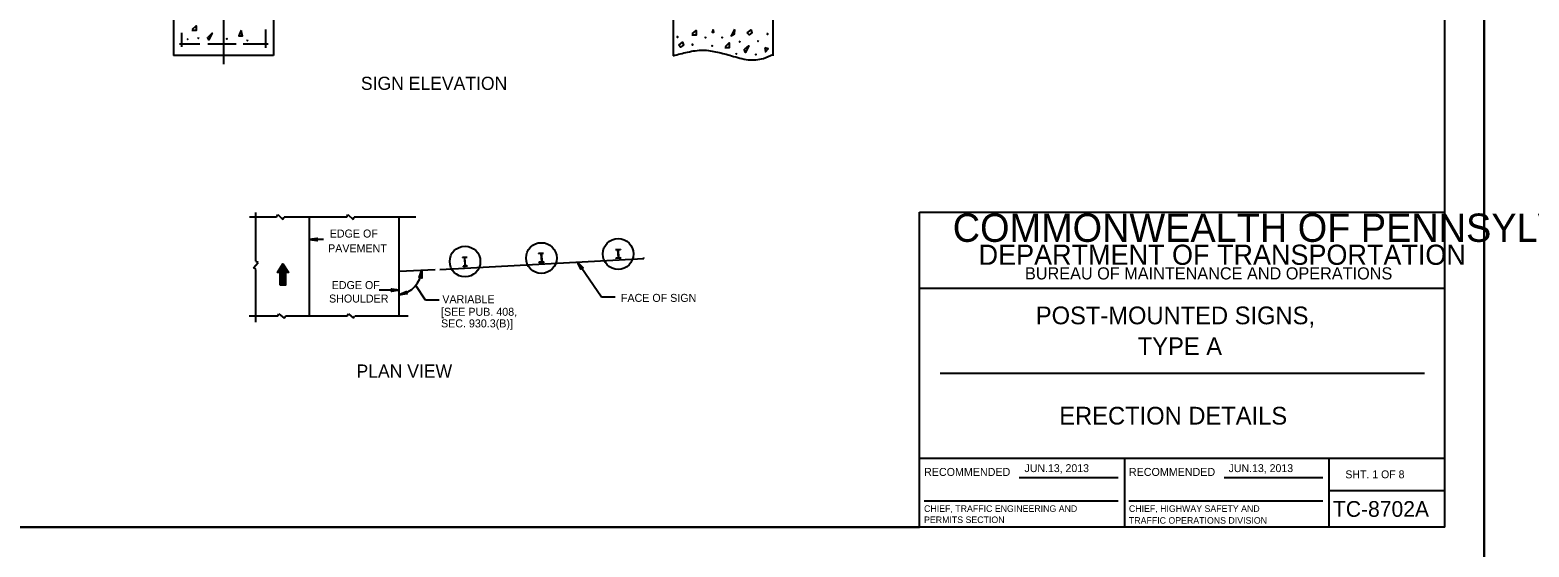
# Model space of a CAD drawing. Extents: x 637580 to 641008, y 294594 to 295782.
# Drawn here: x 637868 to 638438, y 295195 to 295392 of the extents above; entities that cross this region are included whole.
import ezdxf

# ---------------------------------------------------------------- set-up
doc = ezdxf.new("R2010")
doc.units = 0
for name, color, linetype in [('1', 7, 'Continuous'), ('2', 7, 'Continuous'), ('3', 7, 'Continuous'), ('PLT-BNDY', 7, 'Continuous')]:
    doc.layers.add(name, color=color, linetype=linetype)

# ---------------------------------------------------------------- blocks, each defined once
blk = doc.blocks.new('RARROW')
at = {"layer": '3'}
blk.add_lwpolyline([(-2.2695, 0.285), (-2.184875, 0.12075), (0, 0), (-2.2695, 0.285), (-2.38575, 0.384625), (0, 0), (-2.183125, -0.108), (-2.262875, -0.2705), (0, 0), (-2.38575, -0.379125), (-2.262875, -0.2705)], dxfattribs=at)

msp = doc.modelspace()

# ---------------------------------------------------------------- linework, layer by layer
at = {"layer": '1'}
for p, q in [((638406.31, 295202.63), (638406.31, 295766.63)), ((638206.31, 295202.63), (638206.31, 295322.63)), ((638206.31, 295322.63), (638406.31, 295322.63)), ((638406.31, 295293.63), (638206.31, 295293.63)), ((638214.06, 295261.31), (638398.56, 295261.31)), ((638206.31, 295229), (638406.31, 295229)), ((638284.31, 295229), (638284.31, 295202.63)), ((638362.19, 295202.63), (638362.19, 295229)), ((638244.24, 295221.57), (638281.87, 295221.57)), ((638322.24, 295221.57), (638359.87, 295221.57)), ((638362.19, 295216.63), (638406.31, 295216.63)), ((638207.99, 295212.68), (638281.87, 295212.68)), ((638285.99, 295212.68), (638359.87, 295212.68)), ((638406.31, 295202.63), (637620.31, 295202.63)), ((637620.31, 295202.63), (638206.31, 295202.63))]:
    msp.add_line(p, q, dxfattribs=at)
for points in [[(637962.81, 295294.88), (637962.81, 295299.63), (637961.81, 295299.63), (637963.81, 295303), (637965.94, 295299.63), (637964.81, 295299.63), (637964.81, 295294.88), (637962.81, 295294.88)], [(637963.06, 295294.88), (637963.06, 295299.75), (637962.19, 295299.75), (637963.81, 295302.38), (637965.44, 295299.75), (637964.69, 295299.75), (637964.69, 295294.88), (637963.19, 295294.88), (637963.19, 295300.25), (637962.69, 295300), (637963.81, 295301.88), (637965.06, 295300), (637964.31, 295300.25), (637964.31, 295295.25), (637963.44, 295295.25), (637963.44, 295300.5), (637963.81, 295301.13), (637964.31, 295300.5), (637963.81, 295300.5), (637963.81, 295295.38)], [(637963.06, 295294.88), (637962.81, 295294.88)]]:
    msp.add_lwpolyline(points, dxfattribs=at)
at = {"layer": '2'}
for p, q in [((637941.19, 295463.25), (637941.19, 295379)), ((637922.19, 295454.75), (637922.19, 295382.38)), ((637960.31, 295454.13), (637960.31, 295382.38)), ((638112.44, 295420), (638112.44, 295382.25)), ((638150.44, 295409.25), (638150.44, 295382.25)), ((637925.31, 295391), (637925.31, 295385.63)), ((637957.19, 295392.25), (637957.19, 295385.25)), ((637960.31, 295382.38), (637922.19, 295382.38)), ((637932.19, 295386.63), (637924.44, 295386.63)), ((637946.06, 295386.63), (637935.31, 295386.63)), ((637958.19, 295386.63), (637948.69, 295386.63)), ((637961.44, 295320.75), (637951.19, 295320.75)), ((637953.56, 295304), (637953.56, 295322.5)), ((637961.44, 295320.75), (637961.94, 295321.75)), ((637961.94, 295321.75), (637963.81, 295319.88)), ((637963.81, 295319.88), (637964.31, 295320.75)), ((637988.19, 295320.75), (637964.31, 295320.75)), ((637973.94, 295283.25), (637973.94, 295320.75)), ((637988.19, 295320.75), (637988.56, 295321.75)), ((637988.56, 295321.75), (637990.56, 295319.88)), ((637990.56, 295319.88), (637990.94, 295320.75)), ((638014.44, 295320.75), (637990.94, 295320.75)), ((638008.19, 295283.25), (638008.19, 295320.75)), ((637979.31, 295312.25), (637973.94, 295312.25)), ((638092.44, 295308.5), (638090.56, 295308.38)), ((638090.56, 295308.38), (638090.56, 295308.38)), ((638091.31, 295308.38), (638090.56, 295308.38)), ((638091.31, 295308.38), (638091.56, 295305.25)), ((638091.56, 295308.38), (638091.69, 295305.25)), ((638092.44, 295308.38), (638091.56, 295308.38)), ((638092.44, 295308.5), (638092.44, 295308.38)), ((637952.69, 295301.5), (637954.44, 295303.5)), ((637954.44, 295303.5), (637953.56, 295303.88)), ((638023.56, 295300.88), (638101.31, 295305)), ((638034.06, 295305.38), (638032.19, 295305.38)), ((638032.19, 295305.38), (638032.19, 295305.25)), ((638033.06, 295305.38), (638032.19, 295305.25)), ((638034.19, 295302.13), (638032.44, 295301.88)), ((638032.44, 295302.13), (638032.44, 295301.88)), ((638033.19, 295302.13), (638032.44, 295302.13)), ((638033.06, 295305.25), (638033.19, 295302.13)), ((638033.06, 295305.25), (638033.31, 295302.13)), ((638034.06, 295305.38), (638033.19, 295305.38)), ((638033.19, 295303.75), (638033.19, 295303.75)), ((638034.19, 295302.13), (638033.31, 295302.13)), ((638034.06, 295305.38), (638034.06, 295305.38)), ((638034.19, 295302.13), (638034.19, 295302.13)), ((638063.06, 295306.88), (638061.19, 295306.88)), ((638061.19, 295306.88), (638061.19, 295306.75)), ((638062.06, 295306.88), (638061.19, 295306.75)), ((638061.31, 295303.63), (638061.31, 295303.5)), ((638062.31, 295303.63), (638061.31, 295303.63)), ((638063.19, 295303.5), (638061.31, 295303.5)), ((638062.06, 295306.75), (638062.31, 295303.75)), ((638063.06, 295306.88), (638062.31, 295306.88)), ((638062.31, 295306.75), (638062.44, 295303.75)), ((638062.31, 295305.25), (638062.31, 295305.25)), ((638063.19, 295303.75), (638062.44, 295303.63)), ((638063.06, 295306.88), (638063.06, 295306.88)), ((638063.19, 295303.75), (638063.19, 295303.5)), ((638085.19, 295290.25), (638076.08, 295303.66)), ((638092.56, 295305.13), (638090.69, 295305)), ((638090.69, 295305.13), (638090.69, 295305)), ((638091.56, 295305.13), (638090.69, 295305.13)), ((638091.56, 295306.75), (638091.56, 295306.75)), ((638092.56, 295305.25), (638091.69, 295305.13)), ((638092.56, 295305.25), (638092.56, 295305.13)), ((638101.31, 295305), (638101.31, 295305.38)), ((637953.56, 295301), (637952.69, 295301.5)), ((637953.56, 295280.75), (637953.56, 295300.88)), ((638008.19, 295300.17), (638021.81, 295300.88)), ((638008.19, 295293), (638000.56, 295293)), ((638018.19, 295289.13), (638014.45, 295294.73)), ((638090.31, 295290.25), (638085.19, 295290.25)), ((638023.31, 295289.13), (638018.19, 295289.13)), ((637961.94, 295283), (637951.06, 295283)), ((637961.94, 295283), (637962.31, 295284)), ((637962.31, 295284), (637964.31, 295282.25)), ((637964.31, 295282.25), (637964.81, 295283)), ((637988.31, 295283), (637964.81, 295283)), ((637988.31, 295283), (637988.81, 295284)), ((637988.81, 295284), (637990.69, 295282.25)), ((637990.69, 295282.25), (637991.06, 295283)), ((638011.56, 295283), (637991.31, 295283))]:
    msp.add_line(p, q, dxfattribs=at)
for points in [[(637929.44, 295392.38), (637930.81, 295393.63), (637930.81, 295391.88), (637929.19, 295391.88)], [(637927.69, 295388.75), (637927.56, 295388.5), (637927.69, 295388.5), (637927.69, 295388.75)], [(637931.69, 295389.25), (637931.56, 295389), (637931.69, 295389), (637931.69, 295389.25)], [(637935.44, 295389.38), (637936.94, 295390.88), (637935.69, 295388.25), (637935.19, 295389.38)], [(637942.56, 295389), (637942.44, 295388.75), (637942.69, 295388.75), (637942.56, 295389)], [(637947.94, 295392), (637947.06, 295389.88), (637948.44, 295389.88), (637947.94, 295391.75)], [(637950.44, 295388.25), (637950.19, 295388), (637950.44, 295388), (637950.44, 295388.25)], [(638114.19, 295389.75), (638113.94, 295389.38), (638114.19, 295389.38), (638114.19, 295389.63)], [(638114.56, 295386.25), (638116.06, 295387.38), (638116.44, 295386.25), (638115.31, 295385.5), (638114.56, 295386.25)], [(638119.69, 295390.63), (638121.19, 295391.88), (638121.19, 295390.13), (638119.56, 295390.13)], [(638124.81, 295389.5), (638124.69, 295389.25), (638124.94, 295389.25), (638124.81, 295389.38)], [(638127.69, 295392.25), (638127.31, 295391.25), (638127.94, 295391.25), (638127.69, 295392.25)], [(638131.06, 295389.5), (638130.94, 295389.25), (638131.19, 295389.25), (638131.06, 295389.38)], [(638135.81, 295392.38), (638134.56, 295389.88), (638135.81, 295390.63), (638135.94, 295392.13)], [(638137.81, 295387.88), (638137.69, 295387.5), (638137.81, 295387.5), (638137.81, 295387.75)], [(638140.69, 295391), (638142.19, 295392.13), (638142.44, 295391), (638141.44, 295390.25), (638140.69, 295391)], [(638144.81, 295388), (638144.69, 295387.75), (638144.81, 295387.75), (638144.81, 295388)], [(638148.44, 295390.88), (638148.31, 295390.5), (638148.56, 295390.5), (638148.44, 295390.75)], [(638119.94, 295386.75), (638119.69, 295386.38), (638119.94, 295386.38), (638119.94, 295386.63)], [(638127.31, 295386.25), (638127.19, 295386), (638127.44, 295386), (638127.31, 295386.25)], [(638132.44, 295385.75), (638133.81, 295387.13), (638133.81, 295385.25), (638132.19, 295385.25)], [(638136.44, 295383.25), (638136.44, 295383), (638136.56, 295383), (638136.44, 295383.25)], [(638139.69, 295384.75), (638141.31, 295386), (638139.94, 295383.5), (638139.44, 295384.75)], [(638143.94, 295383), (638143.81, 295382.75), (638144.06, 295382.75), (638143.94, 295383)], [(638147.31, 295385.25), (638147.56, 295383.75), (638148.69, 295384.88), (638147.31, 295385.25)]]:
    msp.add_lwpolyline(points, dxfattribs=at)
for centre, major_axis in [((638033.2, 295303.87), (0, 5.85)), ((638062.27, 295305.19), (0, 5.86)), ((638091.51, 295306.74), (0, 5.87))]:
    msp.add_ellipse(centre, major_axis=major_axis, ratio=0.996388, dxfattribs=at)
for centre, major_axis, start_param, end_param in [((638091.34, 295308.28), (0, 0.0425), 4.764749, 6.335545), ((638091.53, 295308.29), (0, -0.0425), 3.193953, 4.764749), ((638033.02, 295305.21), (0, 0.0425), 4.764749, 6.335545), ((638033.21, 295305.22), (0, -0.0425), 3.193953, 4.764749), ((638033.18, 295302.1), (0, 0.0425), 3.193953, 4.764749), ((638033.37, 295302.11), (0, -0.0425), 4.764749, 6.335545), ((638062.1, 295306.74), (0, 0.0425), 4.764749, 6.335545), ((638062.29, 295306.75), (0, -0.0425), 3.193953, 4.764749), ((638062.26, 295303.64), (0, 0.0425), 3.193953, 4.764749), ((638062.45, 295303.65), (0, -0.0425), 4.764749, 6.335545), ((638091.5, 295305.18), (0, 0.0425), 3.193953, 4.764749), ((638091.69, 295305.19), (0, -0.0425), 4.764749, 6.335545), ((638006.74, 295301.09), (0, 10.02), 3.286984, 4.664623)]:
    msp.add_ellipse(centre, major_axis=major_axis, ratio=0.996388, start_param=start_param, end_param=end_param, dxfattribs=at)
msp.add_spline([(638112.44, 295382.25), (638117.94, 295383.63), (638123.81, 295384.38), (638129.31, 295383.63), (638134.69, 295382.25), (638141.06, 295380.75), (638146.81, 295381.25), (638150.44, 295382.75)], degree=3, dxfattribs=at)
at = {"layer": 'PLT-BNDY'}
for points in [[(637580.31, 295781.63), (638421.31, 295781.63), (638421.31, 295187.63), (637580.31, 295187.63)], [(638421.31, 295781.63), (639262.31, 295781.63), (639262.31, 295187.63), (638421.31, 295187.63)]]:
    msp.add_lwpolyline(points, close=True, dxfattribs=at)

# ---------------------------------------------------------------- block references
at = {"layer": '2'}
for p, xscale, yscale, rotation in [((637973.94, 295312.25), 1.2574347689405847, 1.3092961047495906, 180), ((638076.08, 295303.66), 1.2574347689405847, 1.3092961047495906, 124.22439394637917), ((638016.71, 295300.61), 1.257434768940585, 1.3092961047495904, 81.17190166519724), ((638008.19, 295291.18), 1.2574347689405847, 1.3092961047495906, -163.35438489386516)]:
    msp.add_blockref('RARROW', p, dxfattribs=dict(at, xscale=xscale, yscale=yscale, rotation=rotation))
at = {"layer": '2', "xscale": 1.2574347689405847, "yscale": 1.3092961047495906}
msp.add_blockref('RARROW', (638008.19, 295293), dxfattribs=at)

# ---------------------------------------------------------------- texts
at = {"layer": '1'}
for s, height, p in [('COMMONWEALTH OF PENNSYLVANIA', 10.7828, (638218.9, 295311.36)), ('DEPARTMENT OF TRANSPORTATION', 7.6837, (638228.76, 295302.61)), ('BUREAU OF MAINTENANCE AND OPERATIONS', 4.6253, (638246.41, 295297.04)), ('VARIABLE ', 3.043, (638024.56, 295288)), ('POST-MOUNTED SIGNS,', 6.75, (638250.54, 295279.97)), ('TYPE A', 6.75, (638289.35, 295268.22)), ('ERECTION DETAILS', 6.75, (638259.47, 295241.78)), ('RECOMMENDED', 3.048, (638207.99, 295222.2)), ('RECOMMENDED', 3.048, (638285.99, 295222.2)), ('SHT. 1 OF 8', 3, (638368.4, 295221.31)), ('CHIEF, TRAFFIC ENGINEERING AND', 2.5, (638207.99, 295208.51)), ('CHIEF, HIGHWAY SAFETY AND', 2.5, (638285.99, 295208.51)), ('TC-8702A', 6, (638363.68, 295206.63)), ('PERMITS SECTION', 2.5, (638207.99, 295204.26)), ('TRAFFIC OPERATIONS DIVISION', 2.5, (638285.99, 295204.01))]:
    msp.add_text(s, height=height, dxfattribs=at).set_placement(p)
at = {"layer": '2'}
for s, height, p in [('SIGN ELEVATION', 5, (637993.56, 295369.25)), ('PLAN VIEW', 5, (637991.88, 295259.65)), ('JUN.13, 2013', 3, (638246.25, 295223.67)), ('JUN.13, 2013', 3, (638323.97, 295223.67))]:
    msp.add_text(s, height=height, dxfattribs=at).set_placement(p)
at = {"layer": '3'}
for s, height, p in [('EDGE OF', 3.044, (637981.69, 295313)), ('PAVEMENT', 3.043, (637981.06, 295307.38)), ('EDGE OF', 3.044, (637982.44, 295293.38)), ('SHOULDER', 3.043, (637981.44, 295288.25)), ('FACE OF SIGN', 3.0427, (638092.56, 295288.5)), ('[SEE PUB. 408,', 3.0465, (638024.06, 295283.2)), ('SEC. 930.3(B)]', 3.0465, (638024.06, 295278.78))]:
    msp.add_text(s, height=height, dxfattribs=at).set_placement(p)

doc.saveas('drawing.dxf')
